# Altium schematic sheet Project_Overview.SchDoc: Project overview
size A4; Date: Not used; ApprovedBy: Not used; CheckedBy: Not used; Author: Not used; CompanyName: STMicroelectronics; DrawnBy: Not used; Engineer: Not used; Organization: Not used; Address1: Not used; Address2: Not used; Address3: Not used; Address4: Not used; Revision: Not used; SheetNumber: 1; SheetTotal: 8
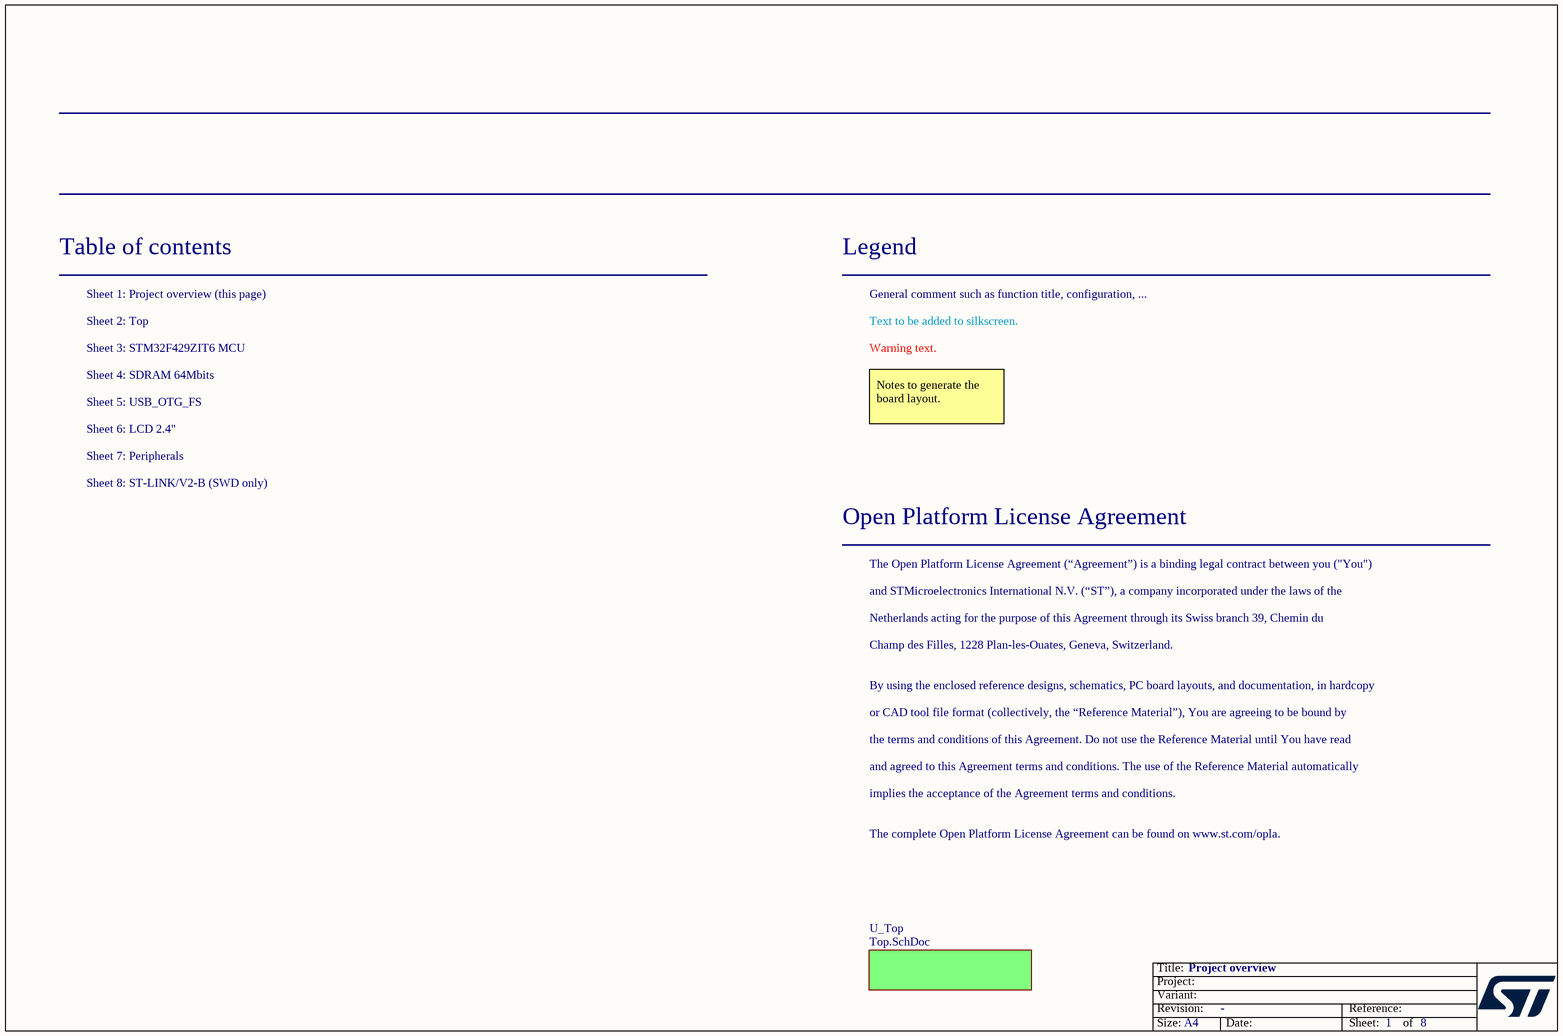
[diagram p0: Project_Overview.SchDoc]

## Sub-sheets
U_Top = Top.SchDoc: no entries

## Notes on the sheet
- Table of contents
- Sheet 1: Project overview (this page)
- Legend
- General comment such as function title, configuration, ...
- Sheet 2: Top
- Sheet 3: STM32F429ZIT6 MCU
- Sheet 4: SDRAM 64Mbits
- Text to be added to silkscreen.
- Warning text.
- Sheet 6: LCD 2.4"
- Sheet 5: USB_OTG_FS
- Notes to generate the board layout.
- Sheet 7: Peripherals
- Sheet 8: ST-LINK/V2-B (SWD only)
- Open Platform License Agreement
- The Open Platform License Agreement (“Agreement”) is a binding legal contract between you ("You")
- and STMicroelectronics International N.V. (“ST”), a company incorporated under the laws of the
- Netherlands acting for the purpose of this Agreement through its Swiss branch 39, Chemin du
- Champ des Filles, 1228 Plan-les-Ouates, Geneva, Switzerland.
- By using the enclosed reference designs, schematics, PC board layouts, and documentation, in hardcopy
- or CAD tool file format (collectively, the “Reference Material”), You are agreeing to be bound by
- the terms and conditions of this Agreement. Do not use the Reference Material until You have read
- and agreed to this Agreement terms and conditions. The use of the Reference Material automatically
- implies the acceptance of the Agreement terms and conditions.
- The complete Open Platform License Agreement can be found on www.st.com/opla.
